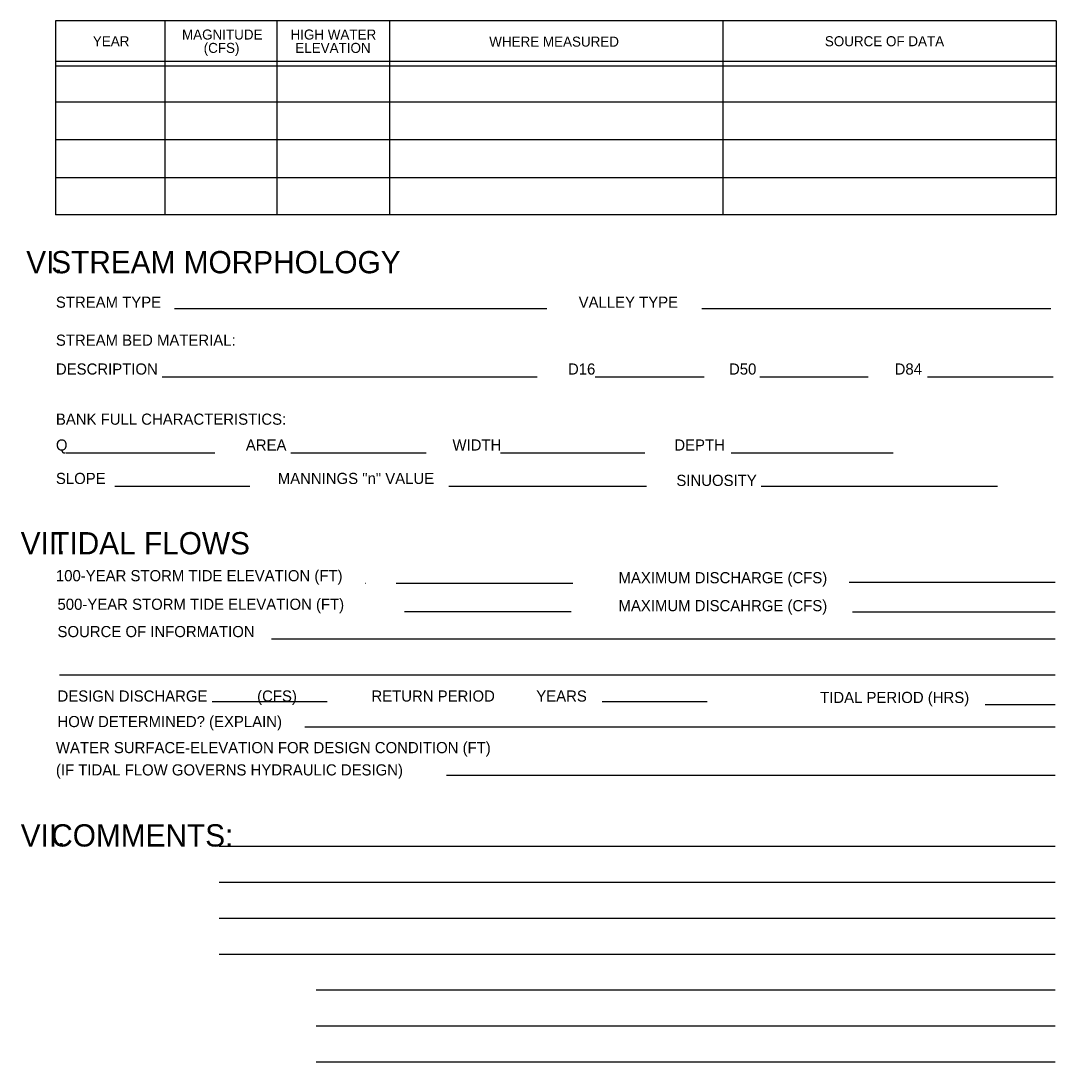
# Model space of a CAD drawing. Extents: x 2.9 to 32.9, y 0.8 to 21.2.
# Drawn here: x 2.89 to 12.03, y 1.97 to 11.17 of the extents above; entities that cross this region are included whole.
import ezdxf

# ---------------------------------------------------------------- set-up
doc = ezdxf.new("R2010")
doc.units = 0
doc.layers.add('G-ANNO-NOTE', color=7, linetype='Continuous')

msp = doc.modelspace()

# ---------------------------------------------------------------- linework, layer by layer
at = {"layer": 'G-ANNO-NOTE'}
for p, q in [((12.0308, 11.1674), (3.1952, 11.1674)), ((3.1952, 11.1674), (3.1952, 9.4544)), ((4.1622, 11.1674), (4.1622, 9.4544)), ((5.1507, 11.1674), (5.1507, 9.4544)), ((6.1444, 11.1674), (6.1444, 9.4544)), ((9.0876, 11.1674), (9.0876, 9.4544)), ((12.0308, 11.1674), (12.0308, 9.4544)), ((12.0308, 10.8073), (3.1952, 10.8073)), ((12.0308, 10.7678), (3.1952, 10.7678)), ((12.0308, 10.4496), (3.1952, 10.4496)), ((12.0308, 10.1152), (3.1952, 10.1152)), ((12.0308, 9.7807), (3.1952, 9.7807)), ((12.0308, 9.4544), (3.1952, 9.4544)), ((7.5354, 8.6238), (4.2454, 8.6238)), ((11.9848, 8.6238), (8.9033, 8.6238)), ((7.448, 8.0199), (4.138, 8.0199)), ((8.9235, 8.0199), (7.9611, 8.0199)), ((10.3723, 8.0199), (9.4132, 8.0199)), ((12.0056, 8.0199), (10.8955, 8.0199)), ((4.6042, 7.3489), (3.2896, 7.3489)), ((6.4687, 7.3489), (5.2749, 7.3489)), ((8.4004, 7.3489), (7.1261, 7.3489)), ((10.5912, 7.3489), (9.1616, 7.3489)), ((4.9127, 7.0537), (3.7188, 7.0537)), ((8.4138, 7.0537), (6.67, 7.0537)), ((11.5132, 7.0537), (9.4276, 7.0537)), ((5.9354, 6.1989), (5.9331, 6.1989)), ((7.7633, 6.1989), (6.205, 6.1989)), ((12.0218, 6.2078), (10.2047, 6.2078)), ((7.7499, 5.9465), (6.2762, 5.9465)), ((12.0218, 5.944), (10.2316, 5.944)), ((12.0218, 5.7071), (5.1041, 5.7071)), ((12.0218, 5.3896), (3.2324, 5.3896)), ((5.5947, 5.1515), (4.5793, 5.1515)), ((8.949, 5.1514), (8.0211, 5.1514)), ((12.0218, 5.1259), (11.4032, 5.1259)), ((12.0218, 4.9293), (5.3973, 4.9293)), ((12.0218, 4.5024), (6.6495, 4.5024)), ((12.0218, 3.8748), (4.6411, 3.8748)), ((12.0218, 3.5574), (4.6411, 3.5574)), ((12.0218, 3.24), (4.6411, 3.24)), ((12.0218, 2.9225), (4.6411, 2.9225)), ((12.0218, 2.6051), (5.4985, 2.6051)), ((12.0218, 2.2877), (5.4985, 2.2877)), ((12.0218, 1.9703), (5.4985, 1.9703))]:
    msp.add_line(p, q, dxfattribs=at)

# ---------------------------------------------------------------- texts
for s, height, p in [('MAGNITUDE', 0.08858, (4.3129, 11.002)), ('HIGH WATER', 0.08858, (5.2709, 11.002)), ('YEAR', 0.08858, (3.526, 10.943)), ('(CFS)', 0.08858, (4.5044, 10.8839)), ('ELEVATION', 0.08858, (5.3135, 10.8839)), ('WHERE MEASURED', 0.088583, (7.0257, 10.9394)), ('SOURCE OF DATA', 0.088583, (9.9887, 10.943)), ('VI. ', 0.19677, (2.9378, 8.9377)), ('STREAM MORPHOLOGY', 0.196772, (3.1583, 8.9377)), ('STREAM TYPE', 0.098425, (3.1998, 8.6333)), ('VALLEY TYPE', 0.098425, (7.815, 8.6333)), ('STREAM BED MATERIAL:', 0.098425, (3.1998, 8.2978)), ('DESCRIPTION', 0.098425, (3.1998, 8.0429)), ('D16', 0.09843, (7.7205, 8.0429)), ('D50', 0.09843, (9.1424, 8.0429)), ('D84', 0.09843, (10.6046, 8.0429)), ('BANK FULL CHARACTERISTICS:', 0.098425, (3.1998, 7.6001)), ('Q', 0.0984, (3.1998, 7.3719)), ('AREA', 0.09843, (4.8767, 7.3719)), ('WIDTH', 0.09843, (6.7011, 7.3719)), ('DEPTH', 0.09843, (8.6596, 7.3719)), ('SLOPE', 0.09843, (3.1998, 7.0767)), ('MANNINGS "n" VALUE', 0.098425, (5.1584, 7.0767)), ('SINUOSITY', 0.09843, (8.6778, 7.0594)), ('VII. ', 0.19677, (2.8889, 6.4551)), ('TIDAL FLOWS', 0.196772, (3.1583, 6.4551)), ('100-YEAR STORM TIDE ELEVATION (FT)', 0.098425, (3.1998, 6.2178)), ('MAXIMUM DISCHARGE (CFS)', 0.098425, (8.1669, 6.2)), ('500-YEAR STORM TIDE ELEVATION (FT)', 0.098425, (3.2139, 5.9654)), ('MAXIMUM DISCAHRGE (CFS)', 0.098425, (8.1669, 5.9531)), ('SOURCE OF INFORMATION', 0.098425, (3.2139, 5.7241)), ('DESIGN DISCHARGE            (CFS)                  RETURN PERIOD          YEARS              ', 0.098425, (3.2139, 5.1549)), ('TIDAL PERIOD (HRS)', 0.098425, (9.9467, 5.1425)), ('HOW DETERMINED? (EXPLAIN)      ', 0.098425, (3.2139, 4.9293)), ('WATER SURFACE-ELEVATION FOR DESIGN CONDITION (FT)', 0.098425, (3.1998, 4.6993)), ('(IF TIDAL FLOW GOVERNS HYDRAULIC DESIGN)', 0.098425, (3.1998, 4.5024)), ('VII. ', 0.19677, (2.8889, 3.8748)), ('COMMENTS:', 0.19677, (3.1583, 3.8748))]:
    msp.add_text(s, height=height, dxfattribs=at).set_placement(p)

doc.saveas('drawing.dxf')
